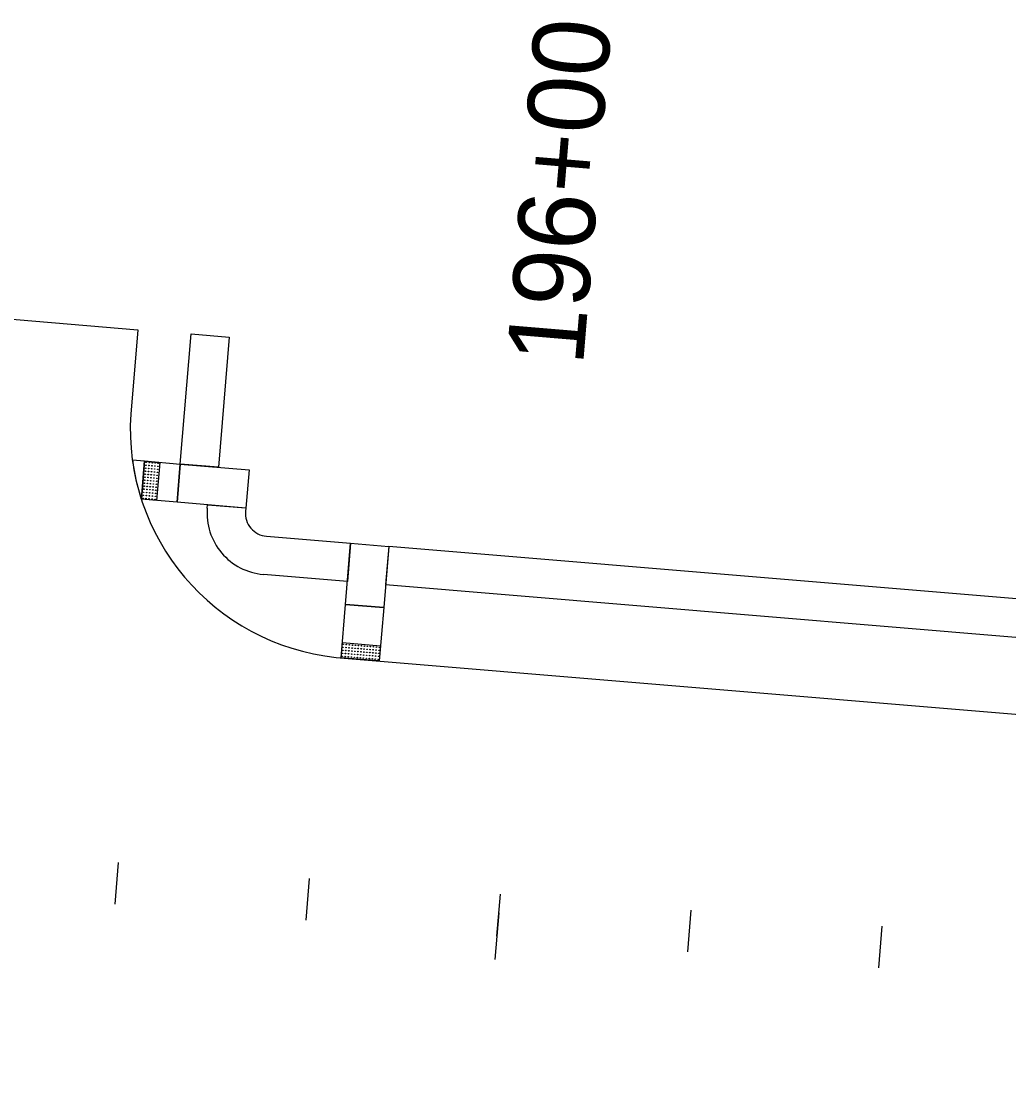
# Model space of a CAD drawing. Extents: x 20499216 to 20505321, y 7953487 to 7960535.
# Drawn here: x 20503240.7 to 20503369.6, y 7953741.4 to 7953880.8 of the extents above; entities that cross this region are included whole.
import ezdxf

# ---------------------------------------------------------------- set-up
doc = ezdxf.new("R2010")
doc.units = 0
for name, color, linetype in [('Drainage', 7, 'Continuous'), ('EXT_CU', 7, 'Continuous'), ('EXT_RR', 7, 'Continuous'), ('NamedBoundary', 7, 'Continuous'), ('Roadways', 7, 'Continuous'), ('Safety', 7, 'Continuous')]:
    doc.layers.add(name, color=color, linetype=linetype)

msp = doc.modelspace()

# ---------------------------------------------------------------- linework, layer by layer
at = {"layer": 'Drainage'}
msp.add_lwpolyline([(20503255.23, 7953823.58), (20503256.82, 7953823.45), (20503256.4, 7953818.46)], dxfattribs=at)
for points in [[(20503256.4, 7953818.46), (20503256.82, 7953823.45), (20503261.48, 7953823.05), (20503261.06, 7953818.07)], [(20503287.45, 7953797.35), (20503282.46, 7953797.76), (20503283.04, 7953804.74), (20503288.03, 7953804.32)]]:
    msp.add_lwpolyline(points, close=True, dxfattribs=at)
msp.add_arc((20503284.95, 7953827.66), 30, 187.819, 197.8548, dxfattribs=at)
at = {"layer": 'EXT_CU'}
for p, q in [((20503256.4, 7953818.46), (20503256.83, 7953823.44)), ((20503256.83, 7953823.44), (20503258.82, 7953823.27)), ((20503258.82, 7953823.27), (20503258.39, 7953818.29)), ((20503258.39, 7953818.29), (20503256.4, 7953818.46)), ((20503282.46, 7953797.76), (20503282.64, 7953799.76)), ((20503282.64, 7953799.76), (20503287.62, 7953799.34)), ((20503287.62, 7953799.34), (20503287.45, 7953797.35)), ((20503287.45, 7953797.35), (20503282.46, 7953797.76))]:
    msp.add_line(p, q, dxfattribs=at)
for points in [[(20503267.88, 7953839.6), (20503266.47, 7953822.64), (20503261.48, 7953823.05), (20503262.9, 7953840.04), (20503267.88, 7953839.62)], [(20503631.86, 7953778.64), (20503869.7, 7953742.74), (20503870.28, 7953747.71), (20503632.44, 7953783.61), (20503288.69, 7953812.3), (20503288.28, 7953807.31)]]:
    msp.add_lwpolyline(points, close=True, dxfattribs=at)
for points in [[(20503265.01, 7953817.29), (20503265.05, 7953817.73), (20503270.03, 7953817.32), (20503270, 7953816.87)], [(20503272.74, 7953813.63), (20503283.71, 7953812.71), (20503283.29, 7953807.73), (20503272.32, 7953808.65)]]:
    msp.add_lwpolyline(points, dxfattribs=at)
for radius in [8, 3]:
    msp.add_arc((20503272.98, 7953816.62), radius, 175.1856, 265.2301, dxfattribs=at)
for centre, major_axis in [((20503256.97, 7953822.5), (0.0241, -0.0288)), ((20503256.97, 7953822.5), (0.0121, -0.0144)), ((20503257, 7953822.89), (0.0241, -0.0288)), ((20503257, 7953822.89), (0.0121, -0.0144)), ((20503257.04, 7953823.28), (0.0241, -0.0288)), ((20503257.04, 7953823.28), (0.0121, -0.0144)), ((20503257.36, 7953822.47), (0.0241, -0.0288)), ((20503257.36, 7953822.47), (0.0121, -0.0144)), ((20503257.39, 7953822.86), (0.0241, -0.0288)), ((20503257.39, 7953822.86), (0.0121, -0.0144)), ((20503257.43, 7953823.25), (0.0241, -0.0288)), ((20503257.43, 7953823.25), (0.0121, -0.0144)), ((20503257.75, 7953822.43), (0.0241, -0.0288)), ((20503257.75, 7953822.43), (0.0121, -0.0144)), ((20503257.78, 7953822.82), (0.0241, -0.0288)), ((20503257.78, 7953822.82), (0.0121, -0.0144)), ((20503257.82, 7953823.21), (0.0241, -0.0288)), ((20503257.82, 7953823.21), (0.0121, -0.0144)), ((20503258.14, 7953822.4), (0.0241, -0.0288)), ((20503258.14, 7953822.4), (0.0121, -0.0144)), ((20503258.17, 7953822.79), (0.0241, -0.0288)), ((20503258.17, 7953822.79), (0.0121, -0.0144)), ((20503258.21, 7953823.18), (0.0241, -0.0288)), ((20503258.21, 7953823.18), (0.0121, -0.0144)), ((20503258.53, 7953822.36), (0.0241, -0.0288)), ((20503258.53, 7953822.36), (0.0121, -0.0144)), ((20503258.56, 7953822.75), (0.0241, -0.0288)), ((20503258.56, 7953822.75), (0.0121, -0.0144)), ((20503258.6, 7953823.14), (0.0241, -0.0288)), ((20503258.6, 7953823.14), (0.0121, -0.0144)), ((20503256.84, 7953820.94), (0.0241, -0.0288)), ((20503256.84, 7953820.94), (0.0121, -0.0144)), ((20503256.87, 7953821.33), (0.0241, -0.0288)), ((20503256.87, 7953821.33), (0.0121, -0.0144)), ((20503256.9, 7953821.72), (0.0241, -0.0288)), ((20503256.9, 7953821.72), (0.0121, -0.0144)), ((20503256.94, 7953822.11), (0.0241, -0.0288)), ((20503256.94, 7953822.11), (0.0121, -0.0144)), ((20503257.23, 7953820.91), (0.0241, -0.0288)), ((20503257.23, 7953820.91), (0.0121, -0.0144)), ((20503257.26, 7953821.3), (0.0241, -0.0288)), ((20503257.26, 7953821.3), (0.0121, -0.0144)), ((20503257.29, 7953821.69), (0.0241, -0.0288)), ((20503257.29, 7953821.69), (0.0121, -0.0144)), ((20503257.33, 7953822.08), (0.0241, -0.0288)), ((20503257.33, 7953822.08), (0.0121, -0.0144)), ((20503257.62, 7953820.87), (0.0241, -0.0288)), ((20503257.62, 7953820.87), (0.0121, -0.0144)), ((20503257.65, 7953821.26), (0.0241, -0.0288)), ((20503257.65, 7953821.26), (0.0121, -0.0144)), ((20503257.68, 7953821.65), (0.0241, -0.0288)), ((20503257.68, 7953821.65), (0.0121, -0.0144)), ((20503257.72, 7953822.04), (0.0241, -0.0288)), ((20503257.72, 7953822.04), (0.0121, -0.0144)), ((20503258.01, 7953820.84), (0.0241, -0.0288)), ((20503258.04, 7953821.23), (0.0241, -0.0288)), ((20503258.04, 7953821.23), (0.0121, -0.0144)), ((20503258.07, 7953821.62), (0.0241, -0.0288)), ((20503258.07, 7953821.62), (0.0121, -0.0144)), ((20503258.11, 7953822.01), (0.0241, -0.0288)), ((20503258.11, 7953822.01), (0.0121, -0.0144)), ((20503258.43, 7953821.19), (0.0241, -0.0288)), ((20503258.43, 7953821.19), (0.0121, -0.0144)), ((20503258.46, 7953821.58), (0.0241, -0.0288)), ((20503258.46, 7953821.58), (0.0121, -0.0144)), ((20503258.5, 7953821.97), (0.0241, -0.0288)), ((20503258.5, 7953821.97), (0.0121, -0.0144)), ((20503256.73, 7953819.77), (0.0241, -0.0288)), ((20503256.73, 7953819.77), (0.0121, -0.0144)), ((20503256.77, 7953820.16), (0.0241, -0.0288)), ((20503256.77, 7953820.16), (0.0121, -0.0144)), ((20503256.8, 7953820.55), (0.0241, -0.0288)), ((20503256.8, 7953820.55), (0.0121, -0.0144)), ((20503257.12, 7953819.74), (0.0241, -0.0288)), ((20503257.12, 7953819.74), (0.0121, -0.0144)), ((20503257.16, 7953820.13), (0.0241, -0.0288)), ((20503257.16, 7953820.13), (0.0121, -0.0144)), ((20503257.19, 7953820.52), (0.0241, -0.0288)), ((20503257.19, 7953820.52), (0.0121, -0.0144)), ((20503257.51, 7953819.7), (0.0241, -0.0288)), ((20503257.51, 7953819.7), (0.0121, -0.0144)), ((20503257.55, 7953820.09), (0.0241, -0.0288)), ((20503257.55, 7953820.09), (0.0121, -0.0144)), ((20503257.58, 7953820.48), (0.0241, -0.0288)), ((20503257.58, 7953820.48), (0.0121, -0.0144)), ((20503257.9, 7953819.67), (0.0241, -0.0288)), ((20503257.9, 7953819.67), (0.0121, -0.0144)), ((20503257.94, 7953820.06), (0.0241, -0.0288)), ((20503257.94, 7953820.06), (0.0121, -0.0144)), ((20503257.97, 7953820.45), (0.0241, -0.0288)), ((20503257.97, 7953820.45), (0.0121, -0.0144)), ((20503258.01, 7953820.84), (0.0121, -0.0144)), ((20503258.29, 7953819.63), (0.0241, -0.0288)), ((20503258.29, 7953819.63), (0.0121, -0.0144)), ((20503258.33, 7953820.02), (0.0241, -0.0288)), ((20503258.33, 7953820.02), (0.0121, -0.0144)), ((20503258.36, 7953820.41), (0.0241, -0.0288)), ((20503258.36, 7953820.41), (0.0121, -0.0144)), ((20503258.4, 7953820.8), (0.0241, -0.0288)), ((20503258.4, 7953820.8), (0.0121, -0.0144)), ((20503256.63, 7953818.58), (0.0241, -0.0288)), ((20503256.63, 7953818.58), (0.0121, -0.0144)), ((20503256.67, 7953818.97), (0.0241, -0.0288)), ((20503256.67, 7953818.97), (0.0121, -0.0144)), ((20503256.7, 7953819.36), (0.0241, -0.0288)), ((20503256.7, 7953819.36), (0.0121, -0.0144)), ((20503257.02, 7953818.55), (0.0241, -0.0288)), ((20503257.02, 7953818.55), (0.0121, -0.0144)), ((20503257.06, 7953818.94), (0.0241, -0.0288)), ((20503257.06, 7953818.94), (0.0121, -0.0144)), ((20503257.09, 7953819.33), (0.0241, -0.0288)), ((20503257.09, 7953819.33), (0.0121, -0.0144)), ((20503257.41, 7953818.51), (0.0241, -0.0288)), ((20503257.41, 7953818.51), (0.0121, -0.0144)), ((20503257.45, 7953818.9), (0.0241, -0.0288)), ((20503257.45, 7953818.9), (0.0121, -0.0144)), ((20503257.48, 7953819.29), (0.0241, -0.0288)), ((20503257.48, 7953819.29), (0.0121, -0.0144)), ((20503257.8, 7953818.48), (0.0241, -0.0288)), ((20503257.8, 7953818.48), (0.0121, -0.0144)), ((20503257.84, 7953818.87), (0.0241, -0.0288)), ((20503257.84, 7953818.87), (0.0121, -0.0144)), ((20503257.87, 7953819.26), (0.0241, -0.0288)), ((20503257.87, 7953819.26), (0.0121, -0.0144)), ((20503258.19, 7953818.44), (0.0241, -0.0288)), ((20503258.19, 7953818.44), (0.0121, -0.0144)), ((20503258.23, 7953818.83), (0.0241, -0.0288)), ((20503258.23, 7953818.83), (0.0121, -0.0144)), ((20503258.26, 7953819.22), (0.0241, -0.0288)), ((20503258.26, 7953819.22), (0.0121, -0.0144)), ((20503282.69, 7953798.74), (-0.0287, -0.0242)), ((20503282.69, 7953798.74), (-0.0144, -0.0121)), ((20503282.72, 7953799.13), (-0.0287, -0.0242)), ((20503282.72, 7953799.13), (-0.0144, -0.0121)), ((20503282.75, 7953799.52), (-0.0287, -0.0242)), ((20503282.75, 7953799.52), (-0.0144, -0.0121)), ((20503283.08, 7953798.71), (-0.0287, -0.0242)), ((20503283.08, 7953798.71), (-0.0144, -0.0121)), ((20503283.11, 7953799.1), (-0.0287, -0.0242)), ((20503283.11, 7953799.1), (-0.0144, -0.0121)), ((20503283.14, 7953799.49), (-0.0287, -0.0242)), ((20503283.14, 7953799.49), (-0.0144, -0.0121)), ((20503283.47, 7953798.68), (-0.0287, -0.0242)), ((20503283.47, 7953798.68), (-0.0144, -0.0121)), ((20503283.5, 7953799.07), (-0.0287, -0.0242)), ((20503283.5, 7953799.07), (-0.0144, -0.0121)), ((20503283.54, 7953799.46), (-0.0287, -0.0242)), ((20503283.54, 7953799.46), (-0.0144, -0.0121)), ((20503283.88, 7953798.64), (-0.0287, -0.0242)), ((20503283.88, 7953798.64), (-0.0144, -0.0121)), ((20503283.91, 7953799.03), (-0.0287, -0.0242)), ((20503283.91, 7953799.03), (-0.0144, -0.0121)), ((20503283.95, 7953799.42), (-0.0287, -0.0242)), ((20503283.95, 7953799.42), (-0.0144, -0.0121)), ((20503284.27, 7953798.61), (-0.0287, -0.0242)), ((20503284.27, 7953798.61), (-0.0144, -0.0121)), ((20503284.3, 7953799), (-0.0287, -0.0242)), ((20503284.3, 7953799), (-0.0144, -0.0121)), ((20503284.34, 7953799.39), (-0.0287, -0.0242)), ((20503284.34, 7953799.39), (-0.0144, -0.0121)), ((20503284.66, 7953798.58), (-0.0287, -0.0242)), ((20503284.66, 7953798.58), (-0.0144, -0.0121)), ((20503284.69, 7953798.97), (-0.0287, -0.0242)), ((20503284.69, 7953798.97), (-0.0144, -0.0121)), ((20503284.73, 7953799.36), (-0.0287, -0.0242)), ((20503284.73, 7953799.36), (-0.0144, -0.0121)), ((20503285.05, 7953798.55), (-0.0287, -0.0242)), ((20503285.08, 7953798.94), (-0.0287, -0.0242)), ((20503285.08, 7953798.94), (-0.0144, -0.0121)), ((20503285.12, 7953799.33), (-0.0287, -0.0242)), ((20503285.12, 7953799.33), (-0.0144, -0.0121)), ((20503285.47, 7953798.9), (-0.0287, -0.0242)), ((20503285.47, 7953798.9), (-0.0144, -0.0121)), ((20503285.51, 7953799.29), (-0.0287, -0.0242)), ((20503285.51, 7953799.29), (-0.0144, -0.0121)), ((20503285.86, 7953798.87), (-0.0287, -0.0242)), ((20503285.86, 7953798.87), (-0.0144, -0.0121)), ((20503285.9, 7953799.26), (-0.0287, -0.0242)), ((20503285.9, 7953799.26), (-0.0144, -0.0121)), ((20503286.25, 7953798.84), (-0.0287, -0.0242)), ((20503286.25, 7953798.84), (-0.0144, -0.0121)), ((20503286.29, 7953799.23), (-0.0287, -0.0242)), ((20503286.29, 7953799.23), (-0.0144, -0.0121)), ((20503286.64, 7953798.81), (-0.0287, -0.0242)), ((20503286.64, 7953798.81), (-0.0144, -0.0121)), ((20503286.68, 7953799.2), (-0.0287, -0.0242)), ((20503286.68, 7953799.2), (-0.0144, -0.0121)), ((20503287.03, 7953798.77), (-0.0287, -0.0242)), ((20503287.03, 7953798.77), (-0.0144, -0.0121)), ((20503287.07, 7953799.16), (-0.0287, -0.0242)), ((20503287.07, 7953799.16), (-0.0144, -0.0121)), ((20503287.42, 7953798.74), (-0.0287, -0.0242)), ((20503287.42, 7953798.74), (-0.0144, -0.0121)), ((20503287.46, 7953799.13), (-0.0287, -0.0242)), ((20503287.46, 7953799.13), (-0.0144, -0.0121)), ((20503282.62, 7953797.96), (-0.0287, -0.0242)), ((20503282.62, 7953797.96), (-0.0144, -0.0121)), ((20503282.65, 7953798.35), (-0.0287, -0.0242)), ((20503282.65, 7953798.35), (-0.0144, -0.0121)), ((20503283.01, 7953797.93), (-0.0287, -0.0242)), ((20503283.01, 7953797.93), (-0.0144, -0.0121)), ((20503283.04, 7953798.32), (-0.0287, -0.0242)), ((20503283.04, 7953798.32), (-0.0144, -0.0121)), ((20503283.4, 7953797.9), (-0.0287, -0.0242)), ((20503283.4, 7953797.9), (-0.0144, -0.0121)), ((20503283.43, 7953798.29), (-0.0287, -0.0242)), ((20503283.43, 7953798.29), (-0.0144, -0.0121)), ((20503283.81, 7953797.86), (-0.0287, -0.0242)), ((20503283.81, 7953797.86), (-0.0144, -0.0121)), ((20503283.85, 7953798.25), (-0.0287, -0.0242)), ((20503283.85, 7953798.25), (-0.0144, -0.0121)), ((20503284.2, 7953797.83), (-0.0287, -0.0242)), ((20503284.2, 7953797.83), (-0.0144, -0.0121)), ((20503284.24, 7953798.22), (-0.0287, -0.0242)), ((20503284.24, 7953798.22), (-0.0144, -0.0121)), ((20503284.59, 7953797.8), (-0.0287, -0.0242)), ((20503284.59, 7953797.8), (-0.0144, -0.0121)), ((20503284.63, 7953798.19), (-0.0287, -0.0242)), ((20503284.63, 7953798.19), (-0.0144, -0.0121)), ((20503284.98, 7953797.77), (-0.0287, -0.0242)), ((20503284.98, 7953797.77), (-0.0144, -0.0121)), ((20503285.02, 7953798.16), (-0.0287, -0.0242)), ((20503285.02, 7953798.16), (-0.0144, -0.0121)), ((20503285.05, 7953798.55), (-0.0144, -0.0121)), ((20503285.37, 7953797.73), (-0.0287, -0.0242)), ((20503285.37, 7953797.73), (-0.0144, -0.0121)), ((20503285.41, 7953798.12), (-0.0287, -0.0242)), ((20503285.41, 7953798.12), (-0.0144, -0.0121)), ((20503285.44, 7953798.51), (-0.0287, -0.0242)), ((20503285.44, 7953798.51), (-0.0144, -0.0121)), ((20503285.76, 7953797.7), (-0.0287, -0.0242)), ((20503285.76, 7953797.7), (-0.0144, -0.0121)), ((20503285.8, 7953798.09), (-0.0287, -0.0242)), ((20503285.8, 7953798.09), (-0.0144, -0.0121)), ((20503285.83, 7953798.48), (-0.0287, -0.0242)), ((20503285.83, 7953798.48), (-0.0144, -0.0121)), ((20503286.15, 7953797.67), (-0.0287, -0.0242)), ((20503286.15, 7953797.67), (-0.0144, -0.0121)), ((20503286.19, 7953798.06), (-0.0287, -0.0242)), ((20503286.19, 7953798.06), (-0.0144, -0.0121)), ((20503286.22, 7953798.45), (-0.0287, -0.0242)), ((20503286.22, 7953798.45), (-0.0144, -0.0121)), ((20503286.54, 7953797.64), (-0.0287, -0.0242)), ((20503286.54, 7953797.64), (-0.0144, -0.0121)), ((20503286.58, 7953798.03), (-0.0287, -0.0242)), ((20503286.58, 7953798.03), (-0.0144, -0.0121)), ((20503286.61, 7953798.42), (-0.0287, -0.0242)), ((20503286.61, 7953798.42), (-0.0144, -0.0121)), ((20503286.93, 7953797.6), (-0.0287, -0.0242)), ((20503286.93, 7953797.6), (-0.0144, -0.0121)), ((20503286.97, 7953797.99), (-0.0287, -0.0242)), ((20503286.97, 7953797.99), (-0.0144, -0.0121)), ((20503287, 7953798.38), (-0.0287, -0.0242)), ((20503287, 7953798.38), (-0.0144, -0.0121)), ((20503287.32, 7953797.57), (-0.0287, -0.0242)), ((20503287.32, 7953797.57), (-0.0144, -0.0121)), ((20503287.36, 7953797.96), (-0.0287, -0.0242)), ((20503287.36, 7953797.96), (-0.0144, -0.0121)), ((20503287.39, 7953798.35), (-0.0287, -0.0242)), ((20503287.39, 7953798.35), (-0.0144, -0.0121))]:
    msp.add_ellipse(centre, major_axis=major_axis, ratio=0.997282, dxfattribs=at)
at = {"layer": 'EXT_RR'}
for p, q in [((20503252.97, 7953765.61), (20503253.43, 7953771.05)), ((20503277.89, 7953763.53), (20503278.34, 7953768.98)), ((20503303.05, 7953764.5), (20503302.54, 7953758.41)), ((20503327.71, 7953759.38), (20503328.17, 7953764.82)), ((20503352.63, 7953757.3), (20503353.08, 7953762.74))]:
    msp.add_line(p, q, dxfattribs=at)
at = {"layer": 'NamedBoundary'}
for points in [[(20503200.24, 7953822.66), (20503202.13, 7953845.11), (20503255.94, 7953840.58), (20503255.01, 7953829.56), (20503255.01, 7953829.56)], [(20503281.84, 7953797.82), (20503630.7, 7953768.71), (20503809.08, 7953741.78), (20504366.9, 7953695.23), (20504431.47, 7953689.85)]]:
    msp.add_lwpolyline(points, dxfattribs=at)
msp.add_arc((20503284.97, 7953827.68), 30.02, 176.411, 264.0048, dxfattribs=at)
at = {"layer": 'Roadways'}
for points in [[(20503261.48, 7953823.05), (20503270.45, 7953822.3), (20503270.03, 7953817.31), (20503261.06, 7953818.07)], [(20503283.71, 7953812.71), (20503288.69, 7953812.3), (20503288.03, 7953804.32), (20503283.04, 7953804.74)]]:
    msp.add_lwpolyline(points, close=True, dxfattribs=at)
at = {"layer": 'Safety'}
msp.add_line((20503302.8, 7953761.46), (20503303.25, 7953766.9), dxfattribs=at)

# ---------------------------------------------------------------- texts
at = {"layer": 'EXT_RR'}
msp.add_text('196+00', height=10.02, rotation=85.2296, dxfattribs=at).set_placement((20503314.03, 7953835.78))

doc.saveas('drawing.dxf')
